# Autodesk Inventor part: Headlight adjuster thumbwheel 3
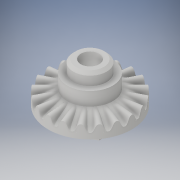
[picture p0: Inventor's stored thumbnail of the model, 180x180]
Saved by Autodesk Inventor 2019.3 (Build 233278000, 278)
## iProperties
Created: 2019-01
Part Number: Headlight adjuster thumbwheel 3
Material: Generic
Document SubType Name: Modeling
Designer: Ben
Density: 1 g/cm^3
Appearance: Default
Author: Ben
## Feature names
1. Extrusion1
2. Revolution1
3. Sweep1
4. Split1
5. Circular Pattern1
6. Hole1
7. Hole2
8. Hole3
## Parameters: d0 = 12.0904 mm, d1 = 3.81 mm, d2 = 0, d4 = 11.7729 mm, d5 = 1.5748 mm, d6 = 4.2164 mm, d8 = 6.3881 mm, d9 = 3.81 mm, d10 = 135 deg, d11 = 2.54 mm, d12 = 3.9116 mm, d13 = 90 deg, d14 = 7.0612 mm, d15 = 19.05 mm, d16 = 3.0226 mm, d17 = 6.35 mm, d18 = 82 deg, d19 = 6.096 mm, d20 = 0, d21 = 25.4 mm, d22 = 25.4 mm, d23 = 5.1816 mm, d24 = 19.05 mm, d25 = 3.0226 mm, d26 = 6.35 mm, d27 = 82 deg, d28 = 6.096 mm, d29 = 0, d30 = 3.683 mm, d35 = 0, d36 = 0, d38 = 360 deg, d40 = 2.032 mm, d43 = 45 deg, d44 = 45 deg, d57 = 25.4 mm, d58 = 25.4 mm, d47 = 4.1402 mm, d48 = 10.0076 mm, d49 = 10.5918 mm, d50 = 2.9972 mm, d51 = 90 deg, d52 = 14.1986 mm, d53 = 0, d54 = 5.08 mm, d65 = 1.12728 mm
